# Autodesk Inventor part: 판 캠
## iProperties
Created: 2012-05
Part Number: 판 캠
Document SubType Name: 모델링
Designer: SeoGD™
Material: 강
Mass: 681.586 g
Surface Area: 331.304 cm^2
Volume: 86.8262 cm^3
Density: 7.85 g/cm^3
변환 표준: STEP AP214IS
파일 이름: C:\Users\SeoGD\Desktop\?쒗뿕\??stp
전처리기: Build: 253, Release: 2010 SP1 - Date: Wed 07/29/2009
전송 단위: 밀리미터
불확실성: 0.01
Author: SeoGD™
